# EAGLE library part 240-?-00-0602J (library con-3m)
Zero Insertion Force Socked Source: http://www.3M.com/ehpd
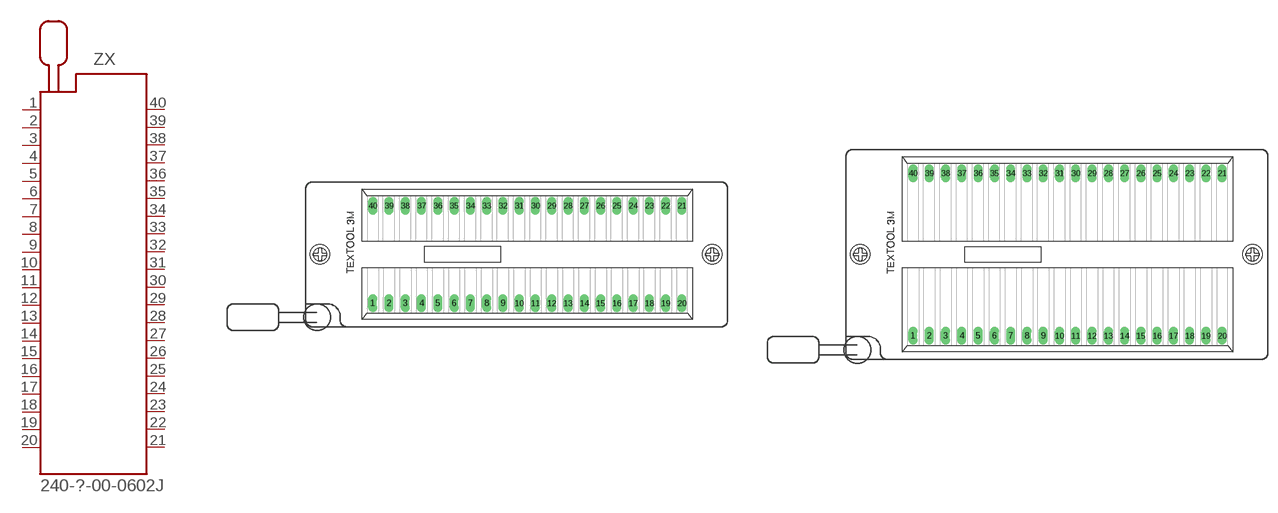
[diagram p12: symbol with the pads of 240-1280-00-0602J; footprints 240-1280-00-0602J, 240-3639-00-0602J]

Designator prefix ZX

## 240-1280-00-0602J (MF: 3M; MPN: 240-1280-00-0602J; OC_FARNELL: 9897364; OC_NEWARK: 85K7848)  [240-1280-00-0602J]
1  1  pas
2  2  pas
3  3  pas
4  4  pas
5  5  pas
6  6  pas
7  7  pas
8  8  pas
9  9  pas
10  10  pas
11  11  pas
12  12  pas
13  13  pas
14  14  pas
15  15  pas
16  16  pas
17  17  pas
18  18  pas
19  19  pas
20  20  pas
21  21  pas
22  22  pas
23  23  pas
24  24  pas
25  25  pas
26  26  pas
27  27  pas
28  28  pas
29  29  pas
30  30  pas
31  31  pas
32  32  pas
33  33  pas
34  34  pas
35  35  pas
36  36  pas
37  37  pas
38  38  pas
39  39  pas
40  40  pas

## 240-3639-00-0602J (MF: 3M; MPN: 240-3639-00-0602J; OC_FARNELL: unknown; OC_NEWARK: 85K7854)  [240-3639-00-0602J]
Pads as for 240-1280-00-0602J

## Footprint 240-1280-00-0602J (pad centres in mm)
3M TEXTOOL 40 pol. DIP Lever actuated zero insertion force mechanism Hersteller: 3M TEXTOOL Herstellerbez.: 240-1280-00-0602J Farnell Best.-Nr.: 4665466 Source: http://www.3M.com/ehpd
drill 0.9 long: 1 -24.13,-7.62; 2 -21.59,-7.62; 3 -19.05,-7.62; 4 -16.51,-7.62; 5 -13.97,-7.62; 6 -11.43,-7.62; 7 -8.89,-7.62; 8 -6.35,-7.62; 9 -3.81,-7.62; 10 -1.27,-7.62; 11 1.27,-7.62; 12 3.81,-7.62; 13 6.35,-7.62; 14 8.89,-7.62; 15 11.43,-7.62; 16 13.97,-7.62; 17 16.51,-7.62; 18 19.05,-7.62; 19 21.59,-7.62; 20 24.13,-7.62; 21 24.13,7.62; 22 21.59,7.62; 23 19.05,7.62; 24 16.51,7.62; 25 13.97,7.62; 26 11.43,7.62; 27 8.89,7.62; 28 6.35,7.62; 29 3.81,7.62; 30 1.27,7.62; 31 -1.27,7.62; 32 -3.81,7.62; 33 -6.35,7.62; 34 -8.89,7.62; 35 -11.43,7.62; 36 -13.97,7.62; 37 -16.51,7.62; 38 -19.05,7.62; 39 -21.59,7.62; 40 -24.13,7.62
hole 2 at 28.86,0
hole 2 at -32.36,0

## Footprint 240-3639-00-0602J (pad centres in mm)
3M TEXTOOL 40 pol. DIP Lever actuated zero insertion force mechanism Hersteller: 3M TEXTOOL Herstellerbez.: 240-3639-00-0602J Source: http://www.3M.com/ehpd
drill 0.9 long: 1 -24.13,-12.7; 2 -21.59,-12.7; 3 -19.05,-12.7; 4 -16.51,-12.7; 5 -13.97,-12.7; 6 -11.43,-12.7; 7 -8.89,-12.7; 8 -6.35,-12.7; 9 -3.81,-12.7; 10 -1.27,-12.7; 11 1.27,-12.7; 12 3.81,-12.7; 13 6.35,-12.7; 14 8.89,-12.7; 15 11.43,-12.7; 16 13.97,-12.7; 17 16.51,-12.7; 18 19.05,-12.7; 19 21.59,-12.7; 20 24.13,-12.7; 21 24.13,12.7; 22 21.59,12.7; 23 19.05,12.7; 24 16.51,12.7; 25 13.97,12.7; 26 11.43,12.7; 27 8.89,12.7; 28 6.35,12.7; 29 3.81,12.7; 30 1.27,12.7; 31 -1.27,12.7; 32 -3.81,12.7; 33 -6.35,12.7; 34 -8.89,12.7; 35 -11.43,12.7; 36 -13.97,12.7; 37 -16.51,12.7; 38 -19.05,12.7; 39 -21.59,12.7; 40 -24.13,12.7
hole 2 at 28.86,0
hole 2 at -32.36,0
